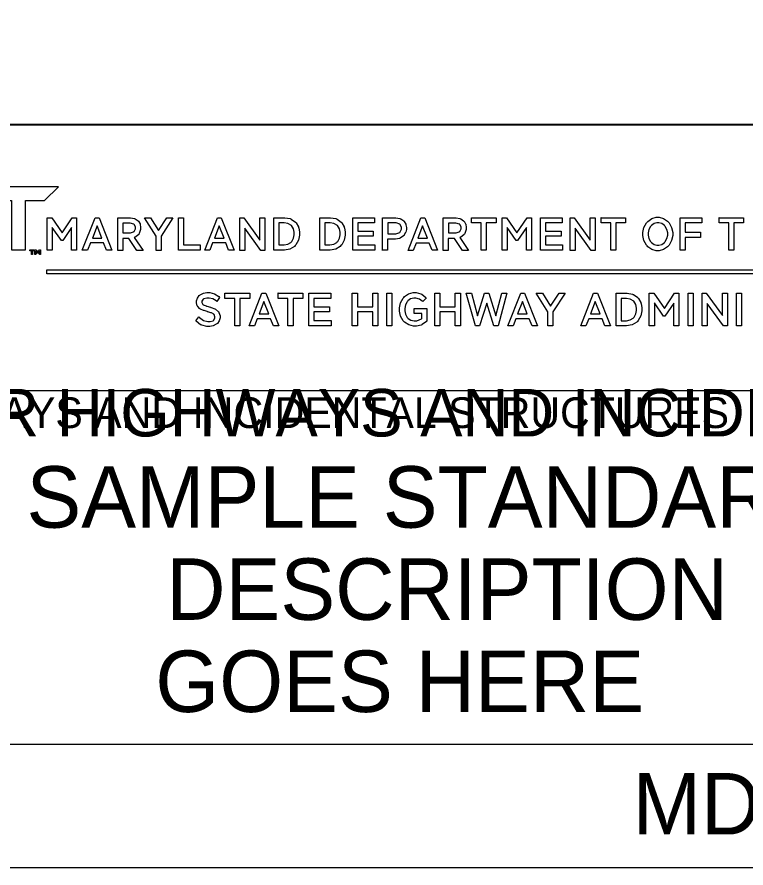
# Model space of a CAD drawing. Extents: x 0 to 1549163, y -476626 to 622136.
# Drawn here: x 4.709 to 6.132, y 5.937 to 7.599 of the extents above; entities that cross this region are included whole.
import ezdxf

# ---------------------------------------------------------------- set-up
doc = ezdxf.new("R2010")
doc.units = 0
for name, color, linetype in [('BORD-LINE', 7, 'Continuous'), ('DETL-NOTE', 7, 'Continuous'), ('MSHA-LOGO', 7, 'Continuous'), ('TTLB-TEXT', 7, 'Continuous'), ('USER-BORD', 7, 'Continuous'), ('USER-LINE', 7, 'Continuous')]:
    doc.layers.add(name, color=color, linetype=linetype)

msp = doc.modelspace()

# ---------------------------------------------------------------- linework, layer by layer
at = {"layer": 'BORD-LINE'}
msp.add_line((7.7685, 7.3883), (0.3943, 7.3883), dxfattribs=at)
at = {"layer": 'MSHA-LOGO'}
for points in [[(4.6335, 7.268), (4.6335, 7.2408), (4.6979, 7.2408), (4.6979, 7.1444), (4.7249, 7.1444), (4.7249, 7.2408), (4.7625, 7.2408), (4.7895, 7.2678), (4.7895, 7.268)], [(4.7677, 7.2075), (4.7766, 7.2075), (4.7968, 7.1779), (4.8165, 7.2075), (4.825, 7.2075), (4.825, 7.144), (4.8152, 7.144), (4.8152, 7.1881), (4.7978, 7.1628), (4.7952, 7.1628), (4.7775, 7.1881), (4.7775, 7.144), (4.7677, 7.144)], [(4.8613, 7.2075), (4.8688, 7.2075), (4.8937, 7.144), (4.8832, 7.144), (4.8777, 7.1582), (4.8518, 7.1582), (4.8463, 7.144), (4.8361, 7.144)], [(4.9052, 7.1437), (4.9052, 7.2072), (4.9274, 7.2072), (4.9302, 7.2072), (4.9377, 7.2058), (4.9386, 7.2055), (4.9393, 7.2053), (4.945, 7.2014), (4.9454, 7.2009), (4.9458, 7.2004), (4.9488, 7.1952), (4.949, 7.1947), (4.9492, 7.1941), (4.95, 7.1889), (4.95, 7.1871), (4.95, 7.1842), (4.9473, 7.1764), (4.9467, 7.1756), (4.9462, 7.1748), (4.9385, 7.169), (4.9376, 7.1687), (4.9546, 7.1433), (4.9425, 7.1433), (4.9271, 7.1667), (4.915, 7.1667), (4.915, 7.1433), (4.9052, 7.1433)], [(4.915, 7.197), (4.915, 7.1776), (4.9278, 7.1776), (4.9299, 7.1776), (4.936, 7.1798), (4.9366, 7.1802), (4.9371, 7.1806), (4.9399, 7.186), (4.9399, 7.1878), (4.9399, 7.1895), (4.9374, 7.1943), (4.9369, 7.1947), (4.9364, 7.1951), (4.9297, 7.197), (4.9274, 7.197)], [(4.9899, 7.1713), (4.9899, 7.1437), (4.9801, 7.1437), (4.9801, 7.1713), (4.9572, 7.2075), (4.9693, 7.2075), (4.985, 7.1822), (5.0011, 7.2075), (5.0128, 7.2075)], [(5.024, 7.2075), (5.0338, 7.2075), (5.0338, 7.1542), (5.0662, 7.1542), (5.0662, 7.144), (5.024, 7.144)], [(5.0999, 7.2075), (5.1074, 7.2075), (5.1323, 7.144), (5.1218, 7.144), (5.1162, 7.1582), (5.0904, 7.1582), (5.0848, 7.144), (5.075, 7.144)], [(5.1846, 7.1437), (5.1532, 7.1871), (5.1532, 7.1437), (5.1437, 7.1437), (5.1437, 7.2072), (5.1513, 7.2072), (5.1827, 7.1638), (5.1827, 7.2072), (5.1922, 7.2072), (5.1922, 7.1437)], [(5.2102, 7.2075), (5.2278, 7.2075), (5.2316, 7.2075), (5.2418, 7.2056), (5.2429, 7.2052), (5.244, 7.2048), (5.2524, 7.199), (5.253, 7.1983), (5.2536, 7.1976), (5.258, 7.1893), (5.2583, 7.1884), (5.2585, 7.1875), (5.2599, 7.1793), (5.2599, 7.1766), (5.2599, 7.1733), (5.2579, 7.1635), (5.2531, 7.1545), (5.2517, 7.1529), (5.2503, 7.1514), (5.2414, 7.1462), (5.2305, 7.144), (5.2269, 7.144), (5.2102, 7.144)], [(5.22, 7.197), (5.22, 7.1542), (5.2275, 7.1542), (5.23, 7.1542), (5.2373, 7.1557), (5.2433, 7.1591), (5.2442, 7.1601), (5.2451, 7.1611), (5.2483, 7.1672), (5.2498, 7.1742), (5.2498, 7.1766), (5.2498, 7.1789), (5.2484, 7.1857), (5.2443, 7.1921), (5.2375, 7.196), (5.2302, 7.1973), (5.2278, 7.1973), (5.22, 7.1973)], [(5.2995, 7.2075), (5.3172, 7.2075), (5.3209, 7.2075), (5.3312, 7.2056), (5.3322, 7.2052), (5.3333, 7.2048), (5.3417, 7.199), (5.3424, 7.1983), (5.3429, 7.1976), (5.3474, 7.1893), (5.3476, 7.1884), (5.3479, 7.1875), (5.3493, 7.1793), (5.3493, 7.1766), (5.3493, 7.1733), (5.3472, 7.1635), (5.3425, 7.1545), (5.3411, 7.1529), (5.3397, 7.1514), (5.3307, 7.1462), (5.3198, 7.144), (5.3162, 7.144), (5.2995, 7.144)], [(5.3096, 7.197), (5.3096, 7.1542), (5.3172, 7.1542), (5.3196, 7.1542), (5.327, 7.1557), (5.333, 7.1591), (5.3339, 7.1601), (5.3348, 7.1611), (5.338, 7.1672), (5.3394, 7.1742), (5.3394, 7.1766), (5.3394, 7.1789), (5.3381, 7.1857), (5.334, 7.1921), (5.3271, 7.196), (5.3199, 7.1973), (5.3175, 7.1973), (5.3096, 7.1973)], [(5.364, 7.2075), (5.4062, 7.2075), (5.4062, 7.1973), (5.3738, 7.1973), (5.3738, 7.1812), (5.4042, 7.1812), (5.4042, 7.1713), (5.3738, 7.1713), (5.3738, 7.1545), (5.4072, 7.1545), (5.4072, 7.1443), (5.364, 7.1443)], [(5.4222, 7.1437), (5.4222, 7.2072), (5.4451, 7.2072), (5.4481, 7.2072), (5.4561, 7.2058), (5.4569, 7.2055), (5.4577, 7.2052), (5.4637, 7.2011), (5.4641, 7.2006), (5.4645, 7.2001), (5.4675, 7.1946), (5.4677, 7.194), (5.4679, 7.1934), (5.4687, 7.1882), (5.4687, 7.1864), (5.4687, 7.1846), (5.4676, 7.1795), (5.4674, 7.1789), (5.4671, 7.1783), (5.4639, 7.1728), (5.4635, 7.1723), (5.463, 7.1718), (5.4568, 7.1677), (5.4559, 7.1674), (5.4551, 7.167), (5.4474, 7.1657), (5.4448, 7.1657), (5.4317, 7.1657), (5.4317, 7.144), (5.4222, 7.144)], [(5.4324, 7.1973), (5.4324, 7.1759), (5.4455, 7.1759), (5.448, 7.1759), (5.4558, 7.1786), (5.4592, 7.1848), (5.4592, 7.1868), (5.4592, 7.1888), (5.456, 7.1946), (5.4486, 7.1973), (5.4461, 7.1973)], [(5.4972, 7.2075), (5.5047, 7.2075), (5.5296, 7.144), (5.5191, 7.144), (5.5135, 7.1578), (5.4877, 7.1578), (5.4821, 7.1437), (5.472, 7.1437)], [(5.5407, 7.1437), (5.5407, 7.2072), (5.5629, 7.2072), (5.5657, 7.2072), (5.5733, 7.2058), (5.5741, 7.2055), (5.5748, 7.2053), (5.5805, 7.2014), (5.5809, 7.2009), (5.5814, 7.2004), (5.5843, 7.1952), (5.5845, 7.1947), (5.5847, 7.1941), (5.5855, 7.1889), (5.5855, 7.1871), (5.5855, 7.1842), (5.5828, 7.1764), (5.5823, 7.1756), (5.5817, 7.1748), (5.5741, 7.169), (5.5731, 7.1687), (5.5901, 7.1433), (5.578, 7.1433), (5.5626, 7.1667), (5.5505, 7.1667), (5.5505, 7.1433), (5.5407, 7.1433)], [(5.5508, 7.197), (5.5508, 7.1776), (5.5636, 7.1776), (5.5658, 7.1776), (5.5719, 7.1798), (5.5724, 7.1802), (5.5729, 7.1806), (5.5757, 7.186), (5.5757, 7.1878), (5.5757, 7.1895), (5.5732, 7.1943), (5.5728, 7.1947), (5.5723, 7.1951), (5.5655, 7.197), (5.5633, 7.197)], [(5.596, 7.2075), (5.6441, 7.2075), (5.6441, 7.1973), (5.6248, 7.1973), (5.6248, 7.144), (5.615, 7.144), (5.615, 7.1973), (5.596, 7.1973)], [(5.6556, 7.2075), (5.6644, 7.2075), (5.6847, 7.1779), (5.7043, 7.2075), (5.7128, 7.2075), (5.7128, 7.144), (5.703, 7.144), (5.703, 7.1881), (5.6857, 7.1628), (5.6831, 7.1628), (5.6654, 7.1881), (5.6654, 7.144), (5.6556, 7.144)], [(5.7305, 7.2075), (5.7727, 7.2075), (5.7727, 7.1973), (5.7403, 7.1973), (5.7403, 7.1812), (5.7707, 7.1812), (5.7707, 7.1713), (5.7403, 7.1713), (5.7403, 7.1545), (5.7737, 7.1545), (5.7737, 7.1443), (5.7305, 7.1443)], [(5.8297, 7.1437), (5.7982, 7.1871), (5.7982, 7.1437), (5.7887, 7.1437), (5.7887, 7.2072), (5.7963, 7.2072), (5.8277, 7.1638), (5.8277, 7.2072), (5.8372, 7.2072), (5.8372, 7.1437)], [(5.8486, 7.2075), (5.8967, 7.2075), (5.8967, 7.1973), (5.8778, 7.1973), (5.8778, 7.144), (5.868, 7.144), (5.868, 7.1973), (5.849, 7.1973), (5.849, 7.2075)], [(5.9389, 7.1986), (5.9403, 7.2002), (5.9482, 7.2057), (5.9567, 7.2082), (5.9595, 7.2082), (5.9624, 7.2082), (5.9708, 7.2059), (5.9788, 7.2005), (5.9802, 7.199), (5.9816, 7.1974), (5.9865, 7.1885), (5.9887, 7.1788), (5.9887, 7.1756), (5.9887, 7.1724), (5.9865, 7.1628), (5.9816, 7.1538), (5.9802, 7.1522), (5.9788, 7.1507), (5.9708, 7.1453), (5.9624, 7.143), (5.9595, 7.143), (5.9567, 7.143), (5.9482, 7.1453), (5.9403, 7.1507), (5.9389, 7.1522), (5.9375, 7.1538), (5.9326, 7.1627), (5.9304, 7.1724), (5.9304, 7.1756), (5.9304, 7.1788), (5.9326, 7.1882), (5.9375, 7.1971)], [(5.9465, 7.1598), (5.9474, 7.1587), (5.9526, 7.1551), (5.958, 7.1536), (5.9599, 7.1536), (5.9617, 7.1536), (5.9672, 7.1551), (5.9724, 7.1587), (5.9733, 7.1598), (5.9742, 7.1608), (5.9774, 7.1667), (5.9789, 7.1734), (5.9789, 7.1756), (5.9789, 7.1778), (5.9774, 7.1845), (5.9742, 7.1904), (5.9733, 7.1914), (5.9724, 7.1925), (5.9672, 7.1961), (5.9617, 7.1976), (5.9599, 7.1976), (5.958, 7.1976), (5.9526, 7.1961), (5.9474, 7.1925), (5.9465, 7.1914), (5.9456, 7.1904), (5.9423, 7.1845), (5.9409, 7.1778), (5.9409, 7.1756), (5.9409, 7.1734), (5.9422, 7.1667), (5.9455, 7.1608)], [(6.0034, 7.2075), (6.0453, 7.2075), (6.0453, 7.1973), (6.0132, 7.1973), (6.0132, 7.1792), (6.043, 7.1792), (6.043, 7.169), (6.0132, 7.169), (6.0132, 7.144), (6.0034, 7.144)], [(6.079, 7.2075), (6.1271, 7.2075), (6.1271, 7.1973), (6.1081, 7.1973), (6.1081, 7.144), (6.0983, 7.144), (6.0983, 7.1973), (6.0793, 7.1973), (6.0793, 7.2075)], [(4.8558, 7.1674), (4.8744, 7.1674), (4.8649, 7.1914)], [(5.0943, 7.1674), (5.113, 7.1674), (5.1035, 7.1914)], [(5.4913, 7.1674), (5.5099, 7.1674), (5.5004, 7.1914)], [(4.7335, 7.1444), (4.7424, 7.1444), (4.7424, 7.1428), (4.739, 7.1428), (4.739, 7.1354), (4.7372, 7.1354), (4.7372, 7.1428), (4.7335, 7.1428)], [(4.7436, 7.1444), (4.7452, 7.1444), (4.7491, 7.14), (4.7527, 7.1444), (4.7544, 7.1444), (4.7544, 7.1354), (4.7523, 7.1354), (4.7523, 7.1418), (4.7489, 7.1377), (4.7455, 7.1418), (4.7455, 7.1354), (4.7436, 7.1354)], [(4.7668, 7.1057), (6.8835, 7.1057), (6.8835, 7.0979), (4.7668, 7.0979)], [(5.0929, 7.0185), (5.0926, 7.0188), (5.0883, 7.0214), (5.0878, 7.0217), (5.0872, 7.0218), (5.0814, 7.0238), (5.0807, 7.0239), (5.0801, 7.0241), (5.0737, 7.0259), (5.0731, 7.0262), (5.0724, 7.0264), (5.0666, 7.0291), (5.066, 7.0294), (5.0655, 7.0297), (5.0613, 7.0343), (5.0609, 7.0348), (5.0606, 7.0354), (5.059, 7.0413), (5.059, 7.0432), (5.059, 7.0449), (5.0607, 7.0502), (5.0644, 7.0552), (5.0654, 7.056), (5.0664, 7.0569), (5.0726, 7.0599), (5.0794, 7.0612), (5.0817, 7.0612), (5.0849, 7.0612), (5.0944, 7.0588), (5.1027, 7.0534), (5.1041, 7.0519), (5.0986, 7.0438), (5.0974, 7.045), (5.0907, 7.0489), (5.0837, 7.0506), (5.0814, 7.0506), (5.0792, 7.0506), (5.0733, 7.049), (5.0728, 7.0486), (5.0722, 7.0483), (5.0692, 7.0442), (5.0692, 7.0429), (5.0692, 7.0416), (5.0714, 7.0381), (5.0718, 7.0377), (5.0722, 7.0374), (5.0778, 7.035), (5.0785, 7.0348), (5.0792, 7.0347), (5.0863, 7.0325), (5.0871, 7.0323), (5.0879, 7.032), (5.0951, 7.0293), (5.0958, 7.0291), (5.0964, 7.0287), (5.102, 7.0239), (5.1025, 7.0233), (5.1029, 7.0226), (5.105, 7.0161), (5.105, 7.014), (5.105, 7.0121), (5.1034, 7.0063), (5.0997, 7.001), (5.0986, 7.0002), (5.0976, 6.9993), (5.0915, 6.9961), (5.0851, 6.9947), (5.083, 6.9947), (5.0793, 6.9947), (5.0695, 6.9974), (5.0683, 6.9979), (5.0671, 6.9985), (5.0581, 7.0055), (5.0574, 7.0063), (5.0635, 7.014), (5.0648, 7.0125), (5.0724, 7.007), (5.081, 7.0047), (5.0839, 7.0047), (5.0859, 7.0047), (5.0914, 7.0063), (5.0919, 7.0066), (5.0924, 7.0069), (5.0948, 7.011), (5.0948, 7.0124), (5.0948, 7.0139), (5.0932, 7.0181)], [(5.1143, 7.0602), (5.1629, 7.0602), (5.1629, 7.0496), (5.1437, 7.0496), (5.1437, 6.996), (5.1338, 6.996), (5.1338, 7.0499), (5.1146, 7.0499), (5.1146, 7.0602)], [(5.1868, 7.0602), (5.1945, 7.0602), (5.2197, 6.996), (5.2092, 6.996), (5.2038, 7.0101), (5.1776, 7.0101), (5.1721, 6.996), (5.1619, 6.996)], [(5.2181, 7.0602), (5.2667, 7.0602), (5.2667, 7.0496), (5.2475, 7.0496), (5.2475, 6.996), (5.2376, 6.996), (5.2376, 7.0499), (5.2185, 7.0499), (5.2185, 7.0602)], [(5.2782, 7.0602), (5.321, 7.0602), (5.321, 7.0496), (5.2881, 7.0496), (5.2881, 7.0336), (5.3188, 7.0336), (5.3188, 7.0236), (5.2881, 7.0236), (5.2881, 7.0066), (5.3217, 7.0066), (5.3217, 6.996), (5.2782, 6.996)], [(5.4031, 7.0233), (5.3731, 7.0233), (5.3731, 6.996), (5.3632, 6.996), (5.3632, 7.0602), (5.3731, 7.0602), (5.3731, 7.0336), (5.4031, 7.0336), (5.4031, 7.0602), (5.413, 7.0602), (5.413, 6.996), (5.4031, 6.996)], [(5.4306, 7.0602), (5.4405, 7.0602), (5.4405, 6.996), (5.4306, 6.996)], [(5.4837, 7.0303), (5.5086, 7.0303), (5.5086, 7.0056), (5.5079, 7.0048), (5.4996, 6.9986), (5.4987, 6.9982), (5.4976, 6.9978), (5.4888, 6.9957), (5.4859, 6.9957), (5.4828, 6.9957), (5.4737, 6.9979), (5.4653, 7.0031), (5.4638, 7.0047), (5.4624, 7.0062), (5.4574, 7.0151), (5.4552, 7.0251), (5.4552, 7.0284), (5.4552, 7.0316), (5.4573, 7.0412), (5.4622, 7.0503), (5.4635, 7.0519), (5.465, 7.0535), (5.4731, 7.0589), (5.4817, 7.0612), (5.4846, 7.0612), (5.4879, 7.0612), (5.497, 7.0588), (5.498, 7.0583), (5.499, 7.0578), (5.5067, 7.0514), (5.5073, 7.0506), (5.5006, 7.0435), (5.4997, 7.0446), (5.4941, 7.0486), (5.4875, 7.0503), (5.4853, 7.0503), (5.4832, 7.0503), (5.4771, 7.0488), (5.4717, 7.0452), (5.4709, 7.0441), (5.47, 7.0432), (5.4668, 7.0372), (5.4654, 7.0304), (5.4654, 7.0281), (5.4654, 7.0258), (5.4669, 7.0188), (5.4702, 7.0128), (5.4712, 7.0117), (5.4721, 7.0108), (5.4777, 7.0074), (5.4838, 7.0059), (5.4859, 7.0059), (5.4891, 7.0059), (5.4981, 7.0097), (5.499, 7.0104), (5.499, 7.0204), (5.4837, 7.0204)], [(5.5642, 7.0233), (5.5341, 7.0233), (5.5341, 6.996), (5.5242, 6.996), (5.5242, 7.0602), (5.5341, 7.0602), (5.5341, 7.0336), (5.5642, 7.0336), (5.5642, 7.0602), (5.5741, 7.0602), (5.5741, 6.996), (5.5642, 6.996)], [(5.6479, 6.996), (5.6396, 6.996), (5.6255, 7.0406), (5.6118, 6.996), (5.6035, 6.996), (5.5856, 7.0602), (5.5958, 7.0602), (5.6079, 7.0159), (5.6214, 7.0602), (5.6294, 7.0602), (5.6431, 7.0159), (5.6549, 7.0602), (5.6648, 7.0602)], [(5.692, 7.0602), (5.6996, 7.0602), (5.7249, 6.996), (5.7143, 6.996), (5.7086, 7.0101), (5.6824, 7.0101), (5.677, 6.996), (5.6667, 6.996)], [(5.7549, 7.0239), (5.7549, 6.996), (5.745, 6.996), (5.745, 7.0239), (5.722, 7.0602), (5.7345, 7.0602), (5.7504, 7.0345), (5.7667, 7.0602), (5.7786, 7.0602)], [(5.8341, 7.0602), (5.8417, 7.0602), (5.867, 6.996), (5.8564, 6.996), (5.851, 7.0101), (5.8248, 7.0101), (5.8193, 6.996), (5.8091, 6.996)], [(5.8781, 7.0602), (5.896, 7.0602), (5.8998, 7.0602), (5.91, 7.058), (5.9111, 7.0576), (5.9121, 7.0572), (5.9206, 7.0514), (5.9213, 7.0506), (5.9219, 7.0498), (5.9264, 7.0416), (5.9267, 7.0406), (5.927, 7.0397), (5.9283, 7.0315), (5.9283, 7.0287), (5.9283, 7.0254), (5.9262, 7.0155), (5.9213, 7.0065), (5.92, 7.005), (5.9186, 7.0035), (5.9096, 6.9982), (5.8987, 6.996), (5.8951, 6.996), (5.8781, 6.996)], [(5.888, 7.0496), (5.888, 7.0063), (5.8957, 7.0063), (5.8982, 7.0063), (5.9056, 7.0078), (5.9117, 7.0113), (5.9127, 7.0124), (5.9136, 7.0134), (5.9168, 7.0196), (5.9181, 7.0265), (5.9181, 7.0287), (5.9181, 7.031), (5.9167, 7.0378), (5.9126, 7.0444), (5.9057, 7.0483), (5.8984, 7.0496), (5.896, 7.0496)], [(5.943, 7.0602), (5.9519, 7.0602), (5.9724, 7.0303), (5.9922, 7.0602), (6.0008, 7.0602), (6.0008, 6.996), (5.9909, 6.996), (5.9909, 7.0406), (5.9734, 7.0152), (5.9708, 7.0152), (5.9529, 7.0409), (5.9529, 6.9963), (5.943, 6.9963)], [(6.0187, 7.0602), (6.0286, 7.0602), (6.0286, 6.996), (6.0187, 6.996)], [(6.0877, 6.996), (6.0561, 7.0397), (6.0561, 6.996), (6.0465, 6.996), (6.0465, 7.0602), (6.0542, 7.0602), (6.0858, 7.0162), (6.0858, 7.0602), (6.0954, 7.0602), (6.0954, 6.996)], [(6.113, 7.0602), (6.1229, 7.0602), (6.1229, 6.996), (6.113, 6.996)], [(5.1811, 7.0197), (5.1999, 7.0197), (5.1903, 7.0441)], [(5.6859, 7.0197), (5.7048, 7.0197), (5.6952, 7.0441)], [(5.8283, 7.0197), (5.8472, 7.0197), (5.8376, 7.0441)]]:
    msp.add_lwpolyline(points, close=True, dxfattribs=at)
at = {"layer": 'TTLB-TEXT'}
msp.add_line((7.7685, 7.3883), (0.3943, 7.3883), dxfattribs=at)
msp.add_lwpolyline([(0.3943, 16.2906), (7.7685, 16.2906), (7.7685, 5.9375), (0.3943, 5.9375)], close=True, dxfattribs=at)
at = {"layer": 'USER-BORD'}
for p, q in [((7.7685, 7.3883), (0.3943, 7.3883)), ((3.2956, 6.1793), (7.7685, 6.1793))]:
    msp.add_line(p, q, dxfattribs=at)
at = {"layer": 'USER-LINE'}
msp.add_lwpolyline([(7.0197, 6.8692), (4.0486, 6.8692), (4.0486, 7.3899), (7.0197, 7.3899)], close=True, dxfattribs=at)

# ---------------------------------------------------------------- texts
at = {"layer": 'DETL-NOTE'}
msp.add_text('STANDARDS FOR HIGHWAYS AND INCIDENTAL STRUCTURES', height=0.09269, dxfattribs=at).set_placement((3.6914, 6.7803))
at = {"layer": 'TTLB-TEXT'}
for s, height, p in [('STANDARDS FOR HIGHWAYS AND INCIDENTAL STRUCTURES', 0.09269, (3.6913, 6.7802)), ('STANDARDS FOR HIGHWAYS AND INCIDENTAL STRUCTURES', 0.06, (3.6914, 6.7966)), ('SAMPLE STANDARD', 0.12, (4.727, 6.6021)), ('DESCRIPTION', 0.12, (4.9998, 6.4221)), ('GOES HERE  ', 0.12, (4.9786, 6.2421)), ('MD 000.00', 0.12, (5.9104, 6.0029))]:
    msp.add_text(s, height=height, dxfattribs=at).set_placement(p)

doc.saveas('drawing.dxf')
